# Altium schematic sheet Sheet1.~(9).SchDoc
size A
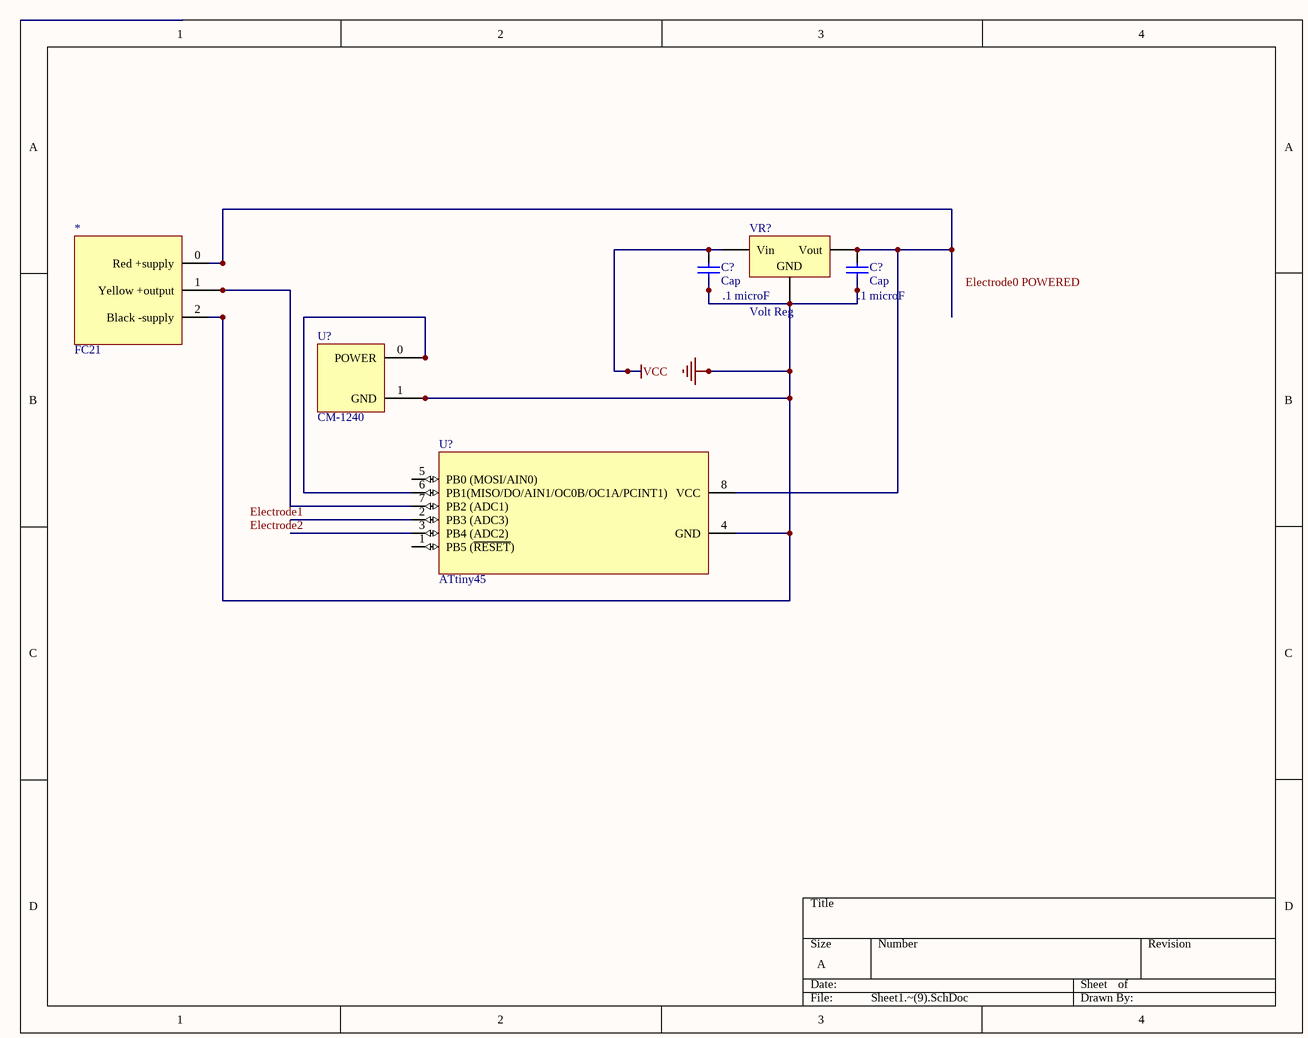
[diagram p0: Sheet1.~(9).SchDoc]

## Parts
(Parts that share a designator on the sheet are numbered #1, #2 ... from top to bottom, then left to right.)
*  FC21  [FC21-Load Cell]
C?#1  Cap  value .1 microF  [VP32-3.2]
C?#2  Cap  value .1 microF  [VP32-3.2]
U?#1  CM-1240  [CMI-1240-buzzer]
U?#2  ATtiny45  [8S2_M]
VR?  Volt Reg  [SOT-23]

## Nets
GND: *.2(Black_-supply) C?#1.1 C?#2.1 U?#1.1(GND) U?#2.4(GND) VR?.3(GND)
VCC: C?#1.2 VR?.2(Vin)
Net*_0: *.0(Red_+supply) C?#2.2 U?#2.8(VCC) VR?.1(Vout)
Net*_1: *.1(Yellow_+output) U?#2.7(PB2_(ADC1))
NetU?#1_0: U?#1.0(POWER) U?#2.6(PB1(MISO/DO/AIN1/OC0B/OC1A/PCINT1))

Not connected (* = marked no-connect by the designer): U?#2 1(PB5_(~{RESET})) 2(PB3_(ADC3)) 3(PB4_(ADC2)) 5(PB0_(MOSI/AIN0))

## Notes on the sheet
- Labels drawn without touching a wire or pin: Electrode0 POWERED, Electrode1, Electrode2

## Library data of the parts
C?#1 C?#2 = Cap: Capacitor
U?#1 = CMI-1240
U?#2 = ATtiny45: 8-Bit AVR Microcontroller with 1K Byte of Flash Memory
VR? = Volt Reg: Voltage Regulator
